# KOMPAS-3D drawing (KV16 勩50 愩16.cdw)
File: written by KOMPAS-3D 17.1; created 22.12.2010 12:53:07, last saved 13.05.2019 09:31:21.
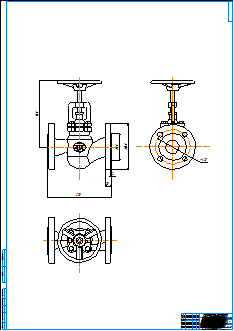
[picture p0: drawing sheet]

Title block, sheet 1: name: KV16 Ду50 Ру16; material: Внимание! Данный продукт является объектом авторского права ООО «Торговый Дом АДЛ». / Запрещается изменение, копирование, распространение / (в том числе путем копирования на другие сайты и ресурсы в Интернете) / или любое иное использование информации и объектов без предварительного / согласия правообладателя (ООО «Торговый Дом АДЛ»).; scale: 1:1; sheets: 1; organisation: ООО "Торговый дом АДЛ"; sheet format: A0; stored path: \\adlc.lan\data\АДЛ_ПКД\3D-модели\ADL production\Вентили ГРАНВЕНТ\KV16\KOMPAS 2D\KV16 Ду50 Ру16.cdw

Views: Спереди 1, Проекционный вид 2, Проекционный вид 3
Dimensions and other numbers on the sheet: 2; 20; 230; 99; 165; 239; 125; 1:1; 1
